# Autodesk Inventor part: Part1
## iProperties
Shininess: 64.0
Length Units: 11269
Angle Units: 11279
Time Units: 11290
Mass Units: 11283
Length Display Precision: 3
Angle Display Precision: 2
Compacted: True
Part Number: Part1
Document SubType Name: Modeling
Created: 2002-12
Designer: deepak
Density: 1 g/cm^3
Density: 0.0
Volumn: 0.0
Area: 0.0
PropertySet Name: Model Information
Control State: 0
Master: False
Checked Out: False
Author: deepak
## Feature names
1. Extrusion1
